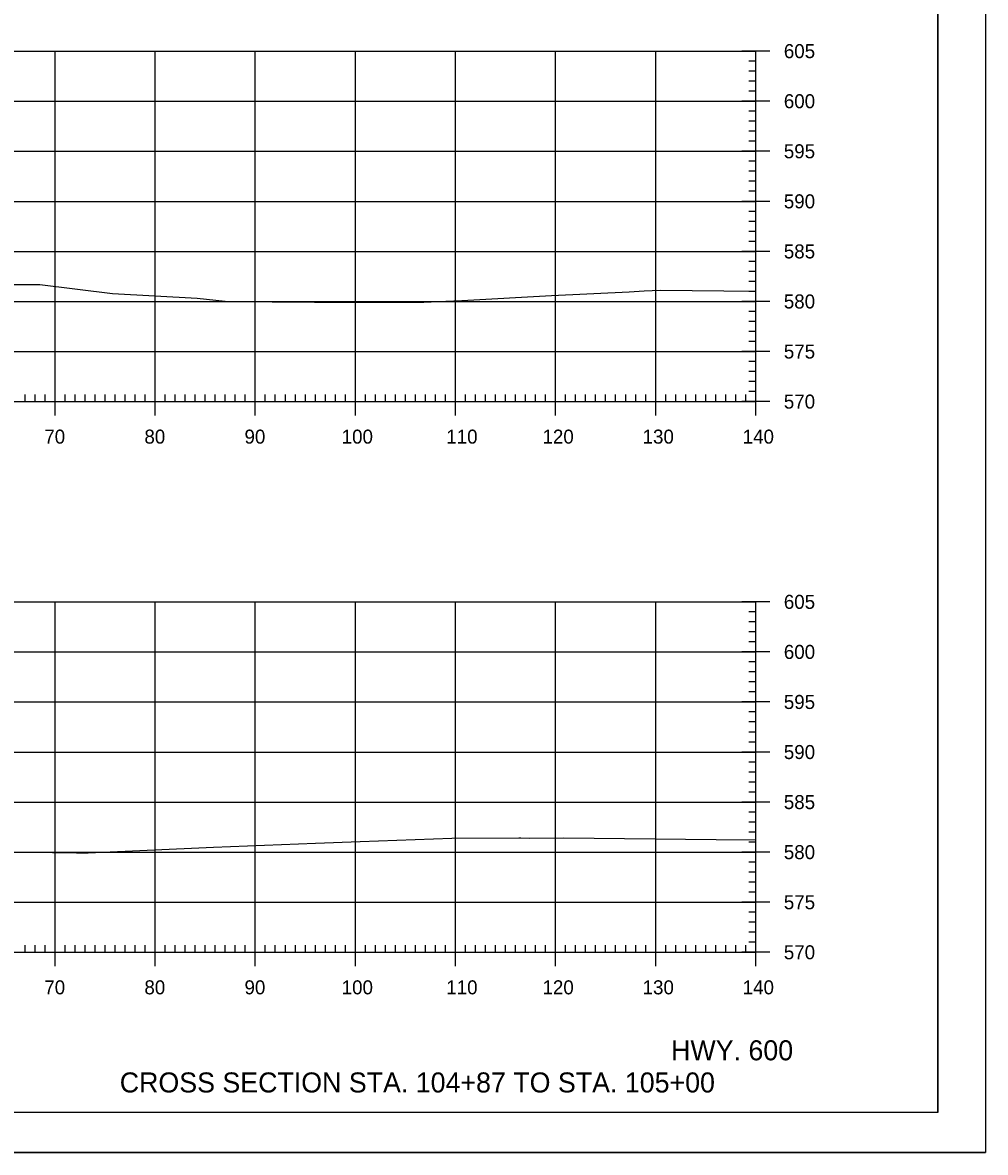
# Model space of a CAD drawing. Extents: x 961436 to 1372525, y 380079 to 2027791.
# Drawn here: x 1370257.3 to 1370353.4, y 380322.4 to 380435.3 of the extents above; entities that cross this region are included whole.
import ezdxf

# ---------------------------------------------------------------- set-up
doc = ezdxf.new("R2010")
doc.units = 0
for name, color, linetype in [('R_Axis', 7, 'Continuous'), ('R_Axis Annot', 7, 'Continuous'), ('R_Draft', 7, 'Continuous'), ('R_Exist Surface', 7, 'Continuous'), ('R_Grid', 7, 'Continuous'), ('R_No Plot', 7, 'Continuous')]:
    doc.layers.add(name, color=color, linetype=linetype)

msp = doc.modelspace()

# ---------------------------------------------------------------- linework, layer by layer
at = {"layer": 'R_Axis'}
for p, q in [((1370331.9, 380432.4), (1370329.1, 380432.4)), ((1370330.5, 380397.4), (1370330.5, 380432.4)), ((1370330.5, 380431.4), (1370329.8, 380431.4)), ((1370330.5, 380430.4), (1370329.8, 380430.4)), ((1370330.5, 380429.4), (1370329.8, 380429.4)), ((1370330.5, 380428.4), (1370329.8, 380428.4)), ((1370331.9, 380427.4), (1370329.1, 380427.4)), ((1370330.5, 380426.4), (1370329.8, 380426.4)), ((1370330.5, 380425.4), (1370329.8, 380425.4)), ((1370330.5, 380424.4), (1370329.8, 380424.4)), ((1370330.5, 380423.4), (1370329.8, 380423.4)), ((1370331.9, 380422.4), (1370329.1, 380422.4)), ((1370330.5, 380421.4), (1370329.8, 380421.4)), ((1370330.5, 380420.4), (1370329.8, 380420.4)), ((1370330.5, 380419.4), (1370329.8, 380419.4)), ((1370330.5, 380418.4), (1370329.8, 380418.4)), ((1370331.9, 380417.4), (1370329.1, 380417.4)), ((1370330.5, 380416.4), (1370329.8, 380416.4)), ((1370330.5, 380415.4), (1370329.8, 380415.4)), ((1370330.5, 380414.4), (1370329.8, 380414.4)), ((1370330.5, 380413.4), (1370329.8, 380413.4)), ((1370331.9, 380412.4), (1370329.1, 380412.4)), ((1370330.5, 380411.4), (1370329.8, 380411.4)), ((1370330.5, 380410.4), (1370329.8, 380410.4)), ((1370330.5, 380409.4), (1370329.8, 380409.4)), ((1370330.5, 380408.4), (1370329.8, 380408.4)), ((1370331.9, 380407.4), (1370329.1, 380407.4)), ((1370330.5, 380406.4), (1370329.8, 380406.4)), ((1370330.5, 380405.4), (1370329.8, 380405.4)), ((1370330.5, 380404.4), (1370329.8, 380404.4)), ((1370331.9, 380402.4), (1370329.1, 380402.4)), ((1370330.5, 380403.4), (1370329.8, 380403.4)), ((1370330.5, 380401.4), (1370329.8, 380401.4)), ((1370330.5, 380400.4), (1370329.8, 380400.4)), ((1370330.5, 380399.4), (1370329.8, 380399.4)), ((1370257.5, 380397.4), (1370257.5, 380398.1)), ((1370258.5, 380397.4), (1370258.5, 380398.1)), ((1370259.5, 380397.4), (1370259.5, 380398.1)), ((1370260.5, 380396), (1370260.5, 380398.8)), ((1370261.5, 380397.4), (1370261.5, 380398.1)), ((1370262.5, 380397.4), (1370262.5, 380398.1)), ((1370263.5, 380397.4), (1370263.5, 380398.1)), ((1370264.5, 380397.4), (1370264.5, 380398.1)), ((1370265.5, 380397.4), (1370265.5, 380398.1)), ((1370266.5, 380397.4), (1370266.5, 380398.1)), ((1370267.5, 380397.4), (1370267.5, 380398.1)), ((1370268.5, 380397.4), (1370268.5, 380398.1)), ((1370269.5, 380397.4), (1370269.5, 380398.1)), ((1370270.5, 380396), (1370270.5, 380398.8)), ((1370271.5, 380397.4), (1370271.5, 380398.1)), ((1370272.5, 380397.4), (1370272.5, 380398.1)), ((1370273.5, 380397.4), (1370273.5, 380398.1)), ((1370274.5, 380397.4), (1370274.5, 380398.1)), ((1370275.5, 380397.4), (1370275.5, 380398.1)), ((1370276.5, 380397.4), (1370276.5, 380398.1)), ((1370277.5, 380397.4), (1370277.5, 380398.1)), ((1370278.5, 380397.4), (1370278.5, 380398.1)), ((1370279.5, 380397.4), (1370279.5, 380398.1)), ((1370280.5, 380396), (1370280.5, 380398.8)), ((1370281.5, 380397.4), (1370281.5, 380398.1)), ((1370282.5, 380397.4), (1370282.5, 380398.1)), ((1370283.5, 380397.4), (1370283.5, 380398.1)), ((1370284.5, 380397.4), (1370284.5, 380398.1)), ((1370285.5, 380397.4), (1370285.5, 380398.1)), ((1370286.5, 380397.4), (1370286.5, 380398.1)), ((1370287.5, 380397.4), (1370287.5, 380398.1)), ((1370288.5, 380397.4), (1370288.5, 380398.1)), ((1370289.5, 380397.4), (1370289.5, 380398.1)), ((1370290.5, 380396), (1370290.5, 380398.8)), ((1370291.5, 380397.4), (1370291.5, 380398.1)), ((1370292.5, 380397.4), (1370292.5, 380398.1)), ((1370293.5, 380397.4), (1370293.5, 380398.1)), ((1370294.5, 380397.4), (1370294.5, 380398.1)), ((1370295.5, 380397.4), (1370295.5, 380398.1)), ((1370296.5, 380397.4), (1370296.5, 380398.1)), ((1370297.5, 380397.4), (1370297.5, 380398.1)), ((1370298.5, 380397.4), (1370298.5, 380398.1)), ((1370299.5, 380397.4), (1370299.5, 380398.1)), ((1370300.5, 380396), (1370300.5, 380398.8)), ((1370301.5, 380397.4), (1370301.5, 380398.1)), ((1370302.5, 380397.4), (1370302.5, 380398.1)), ((1370303.5, 380397.4), (1370303.5, 380398.1)), ((1370304.5, 380397.4), (1370304.5, 380398.1)), ((1370305.5, 380397.4), (1370305.5, 380398.1)), ((1370306.5, 380397.4), (1370306.5, 380398.1)), ((1370307.5, 380397.4), (1370307.5, 380398.1)), ((1370308.5, 380397.4), (1370308.5, 380398.1)), ((1370309.5, 380397.4), (1370309.5, 380398.1)), ((1370310.5, 380396), (1370310.5, 380398.8)), ((1370311.5, 380397.4), (1370311.5, 380398.1)), ((1370312.5, 380397.4), (1370312.5, 380398.1)), ((1370313.5, 380397.4), (1370313.5, 380398.1)), ((1370314.5, 380397.4), (1370314.5, 380398.1)), ((1370315.5, 380397.4), (1370315.5, 380398.1)), ((1370316.5, 380397.4), (1370316.5, 380398.1)), ((1370317.5, 380397.4), (1370317.5, 380398.1)), ((1370318.5, 380397.4), (1370318.5, 380398.1)), ((1370319.5, 380397.4), (1370319.5, 380398.1)), ((1370320.5, 380396), (1370320.5, 380398.8)), ((1370321.5, 380397.4), (1370321.5, 380398.1)), ((1370322.5, 380397.4), (1370322.5, 380398.1)), ((1370323.5, 380397.4), (1370323.5, 380398.1)), ((1370324.5, 380397.4), (1370324.5, 380398.1)), ((1370325.5, 380397.4), (1370325.5, 380398.1)), ((1370326.5, 380397.4), (1370326.5, 380398.1)), ((1370327.5, 380397.4), (1370327.5, 380398.1)), ((1370328.5, 380397.4), (1370328.5, 380398.1)), ((1370329.5, 380397.4), (1370329.5, 380398.1)), ((1370330.5, 380398.4), (1370329.8, 380398.4)), ((1370330.5, 380396), (1370330.5, 380398.8)), ((1370050.5, 380397.4), (1370330.5, 380397.4)), ((1370331.9, 380397.4), (1370329.1, 380397.4)), ((1370331.9, 380377.4), (1370329.1, 380377.4)), ((1370330.5, 380342.4), (1370330.5, 380377.4)), ((1370330.5, 380376.4), (1370329.8, 380376.4)), ((1370330.5, 380375.4), (1370329.8, 380375.4)), ((1370330.5, 380374.4), (1370329.8, 380374.4)), ((1370330.5, 380373.4), (1370329.8, 380373.4)), ((1370331.9, 380372.4), (1370329.1, 380372.4)), ((1370330.5, 380371.4), (1370329.8, 380371.4)), ((1370330.5, 380370.4), (1370329.8, 380370.4)), ((1370330.5, 380369.4), (1370329.8, 380369.4)), ((1370331.9, 380367.4), (1370329.1, 380367.4)), ((1370330.5, 380368.4), (1370329.8, 380368.4)), ((1370330.5, 380366.4), (1370329.8, 380366.4)), ((1370330.5, 380365.4), (1370329.8, 380365.4)), ((1370330.5, 380364.4), (1370329.8, 380364.4)), ((1370330.5, 380363.4), (1370329.8, 380363.4)), ((1370331.9, 380362.4), (1370329.1, 380362.4)), ((1370330.5, 380361.4), (1370329.8, 380361.4)), ((1370330.5, 380360.4), (1370329.8, 380360.4)), ((1370330.5, 380359.4), (1370329.8, 380359.4)), ((1370330.5, 380358.4), (1370329.8, 380358.4)), ((1370331.9, 380357.4), (1370329.1, 380357.4)), ((1370330.5, 380356.4), (1370329.8, 380356.4)), ((1370330.5, 380355.4), (1370329.8, 380355.4)), ((1370330.5, 380354.4), (1370329.8, 380354.4)), ((1370330.5, 380353.4), (1370329.8, 380353.4)), ((1370331.9, 380352.4), (1370329.1, 380352.4)), ((1370330.5, 380351.4), (1370329.8, 380351.4)), ((1370330.5, 380350.4), (1370329.8, 380350.4)), ((1370330.5, 380349.4), (1370329.8, 380349.4)), ((1370330.5, 380348.4), (1370329.8, 380348.4)), ((1370331.9, 380347.4), (1370329.1, 380347.4)), ((1370330.5, 380346.4), (1370329.8, 380346.4)), ((1370330.5, 380345.4), (1370329.8, 380345.4)), ((1370260.5, 380341), (1370260.5, 380343.8)), ((1370270.5, 380341), (1370270.5, 380343.8)), ((1370280.5, 380341), (1370280.5, 380343.8)), ((1370290.5, 380341), (1370290.5, 380343.8)), ((1370300.5, 380341), (1370300.5, 380343.8)), ((1370310.5, 380341), (1370310.5, 380343.8)), ((1370320.5, 380341), (1370320.5, 380343.8)), ((1370330.5, 380344.4), (1370329.8, 380344.4)), ((1370330.5, 380341), (1370330.5, 380343.8)), ((1370257.5, 380342.4), (1370257.5, 380343.1)), ((1370258.5, 380342.4), (1370258.5, 380343.1)), ((1370259.5, 380342.4), (1370259.5, 380343.1)), ((1370261.5, 380342.4), (1370261.5, 380343.1)), ((1370262.5, 380342.4), (1370262.5, 380343.1)), ((1370263.5, 380342.4), (1370263.5, 380343.1)), ((1370264.5, 380342.4), (1370264.5, 380343.1)), ((1370265.5, 380342.4), (1370265.5, 380343.1)), ((1370266.5, 380342.4), (1370266.5, 380343.1)), ((1370267.5, 380342.4), (1370267.5, 380343.1)), ((1370268.5, 380342.4), (1370268.5, 380343.1)), ((1370269.5, 380342.4), (1370269.5, 380343.1)), ((1370271.5, 380342.4), (1370271.5, 380343.1)), ((1370272.5, 380342.4), (1370272.5, 380343.1)), ((1370273.5, 380342.4), (1370273.5, 380343.1)), ((1370274.5, 380342.4), (1370274.5, 380343.1)), ((1370275.5, 380342.4), (1370275.5, 380343.1)), ((1370276.5, 380342.4), (1370276.5, 380343.1)), ((1370277.5, 380342.4), (1370277.5, 380343.1)), ((1370278.5, 380342.4), (1370278.5, 380343.1)), ((1370279.5, 380342.4), (1370279.5, 380343.1)), ((1370281.5, 380342.4), (1370281.5, 380343.1)), ((1370282.5, 380342.4), (1370282.5, 380343.1)), ((1370283.5, 380342.4), (1370283.5, 380343.1)), ((1370284.5, 380342.4), (1370284.5, 380343.1)), ((1370285.5, 380342.4), (1370285.5, 380343.1)), ((1370286.5, 380342.4), (1370286.5, 380343.1)), ((1370287.5, 380342.4), (1370287.5, 380343.1)), ((1370288.5, 380342.4), (1370288.5, 380343.1)), ((1370289.5, 380342.4), (1370289.5, 380343.1)), ((1370291.5, 380342.4), (1370291.5, 380343.1)), ((1370292.5, 380342.4), (1370292.5, 380343.1)), ((1370293.5, 380342.4), (1370293.5, 380343.1)), ((1370294.5, 380342.4), (1370294.5, 380343.1)), ((1370295.5, 380342.4), (1370295.5, 380343.1)), ((1370296.5, 380342.4), (1370296.5, 380343.1)), ((1370297.5, 380342.4), (1370297.5, 380343.1)), ((1370298.5, 380342.4), (1370298.5, 380343.1)), ((1370299.5, 380342.4), (1370299.5, 380343.1)), ((1370301.5, 380342.4), (1370301.5, 380343.1)), ((1370302.5, 380342.4), (1370302.5, 380343.1)), ((1370303.5, 380342.4), (1370303.5, 380343.1)), ((1370304.5, 380342.4), (1370304.5, 380343.1)), ((1370305.5, 380342.4), (1370305.5, 380343.1)), ((1370306.5, 380342.4), (1370306.5, 380343.1)), ((1370307.5, 380342.4), (1370307.5, 380343.1)), ((1370308.5, 380342.4), (1370308.5, 380343.1)), ((1370309.5, 380342.4), (1370309.5, 380343.1)), ((1370311.5, 380342.4), (1370311.5, 380343.1)), ((1370312.5, 380342.4), (1370312.5, 380343.1)), ((1370313.5, 380342.4), (1370313.5, 380343.1)), ((1370314.5, 380342.4), (1370314.5, 380343.1)), ((1370315.5, 380342.4), (1370315.5, 380343.1)), ((1370316.5, 380342.4), (1370316.5, 380343.1)), ((1370317.5, 380342.4), (1370317.5, 380343.1)), ((1370318.5, 380342.4), (1370318.5, 380343.1)), ((1370319.5, 380342.4), (1370319.5, 380343.1)), ((1370321.5, 380342.4), (1370321.5, 380343.1)), ((1370322.5, 380342.4), (1370322.5, 380343.1)), ((1370323.5, 380342.4), (1370323.5, 380343.1)), ((1370324.5, 380342.4), (1370324.5, 380343.1)), ((1370325.5, 380342.4), (1370325.5, 380343.1)), ((1370326.5, 380342.4), (1370326.5, 380343.1)), ((1370327.5, 380342.4), (1370327.5, 380343.1)), ((1370328.5, 380342.4), (1370328.5, 380343.1)), ((1370329.5, 380342.4), (1370329.5, 380343.1)), ((1370330.5, 380343.4), (1370329.8, 380343.4)), ((1370050.5, 380342.4), (1370330.5, 380342.4)), ((1370331.9, 380342.4), (1370329.1, 380342.4))]:
    msp.add_line(p, q, dxfattribs=at)
at = {"layer": 'R_Exist Surface'}
for points in [[(1370251.88, 380409.09), (1370258.99, 380409.09), (1370266.25, 380408.18), (1370274.68, 380407.74), (1370277.5, 380407.42), (1370282.17, 380407.35), (1370286.41, 380407.33), (1370297.34, 380407.32), (1370299.55, 380407.42), (1370301.12, 380407.48), (1370310.08, 380407.98), (1370317.84, 380408.36), (1370319.35, 380408.45), (1370320.94, 380408.52), (1370330.5, 380408.42)], [(1370252.95, 380352.45), (1370257.8, 380352.39), (1370262.63, 380352.32), (1370263.81, 380352.32), (1370276.32, 380352.91), (1370286.52, 380353.29), (1370290.96, 380353.48), (1370300.14, 380353.8), (1370306.83, 380353.82), (1370307.03, 380353.82), (1370307.88, 380353.81), (1370311.28, 380353.83), (1370326.53, 380353.67), (1370330.5, 380353.62)]]:
    msp.add_lwpolyline(points, dxfattribs=at)
at = {"layer": 'R_Grid'}
for p, q in [((1370050.5, 380432.4), (1370330.5, 380432.4)), ((1370260.5, 380397.4), (1370260.5, 380432.4)), ((1370270.5, 380397.4), (1370270.5, 380432.4)), ((1370280.5, 380397.4), (1370280.5, 380432.4)), ((1370290.5, 380397.4), (1370290.5, 380432.4)), ((1370300.5, 380397.4), (1370300.5, 380432.4)), ((1370310.5, 380397.4), (1370310.5, 380432.4)), ((1370320.5, 380397.4), (1370320.5, 380432.4)), ((1370330.5, 380397.4), (1370330.5, 380432.4)), ((1370050.5, 380427.4), (1370330.5, 380427.4)), ((1370050.5, 380422.4), (1370330.5, 380422.4)), ((1370050.5, 380417.4), (1370330.5, 380417.4)), ((1370050.5, 380412.4), (1370330.5, 380412.4)), ((1370050.5, 380407.4), (1370330.5, 380407.4)), ((1370050.5, 380402.4), (1370330.5, 380402.4)), ((1370050.5, 380397.4), (1370330.5, 380397.4)), ((1370050.5, 380377.4), (1370330.5, 380377.4)), ((1370260.5, 380342.4), (1370260.5, 380377.4)), ((1370270.5, 380342.4), (1370270.5, 380377.4)), ((1370280.5, 380342.4), (1370280.5, 380377.4)), ((1370290.5, 380342.4), (1370290.5, 380377.4)), ((1370300.5, 380342.4), (1370300.5, 380377.4)), ((1370310.5, 380342.4), (1370310.5, 380377.4)), ((1370320.5, 380342.4), (1370320.5, 380377.4)), ((1370330.5, 380342.4), (1370330.5, 380377.4)), ((1370050.5, 380372.4), (1370330.5, 380372.4)), ((1370050.5, 380367.4), (1370330.5, 380367.4)), ((1370050.5, 380362.4), (1370330.5, 380362.4)), ((1370050.5, 380357.4), (1370330.5, 380357.4)), ((1370050.5, 380352.4), (1370330.5, 380352.4)), ((1370050.5, 380347.4), (1370330.5, 380347.4)), ((1370050.5, 380342.4), (1370330.5, 380342.4))]:
    msp.add_line(p, q, dxfattribs=at)
at = {"layer": 'R_No Plot'}
for p, q in [((1370348.68, 380326.4), (1370348.68, 380531.86)), ((1370348.68, 380326.4), (1370032.5, 380326.4)), ((1370020.1, 380322.42), (1370353.44, 380322.42))]:
    msp.add_line(p, q, dxfattribs=at)
for points in [[(1370020.1, 380535.75), (1370353.44, 380535.75), (1370353.44, 380322.41), (1370020.1, 380322.41)], [(1370266.42, 380531.86), (1370286.04, 380531.86), (1370286.04, 380521.98), (1370302.16, 380521.98), (1370325.36, 380521.98), (1370325.48, 380493.82), (1370348.68, 380493.82), (1370348.68, 380326.4), (1370032.5, 380326.4), (1370032.5, 380531.86)]]:
    msp.add_lwpolyline(points, close=True, dxfattribs=at)

# ---------------------------------------------------------------- texts
at = {"layer": 'R_Axis Annot'}
for s, p in [('605', (1370333.3, 380431.7)), ('600', (1370333.3, 380426.7)), ('595', (1370333.3, 380421.7)), ('590', (1370333.3, 380416.7)), ('585', (1370333.3, 380411.7)), ('580', (1370333.3, 380406.7)), ('575', (1370333.3, 380401.7)), ('570', (1370333.3, 380396.7)), ('70', (1370259.42, 380393.2)), ('80', (1370269.42, 380393.2)), ('90', (1370279.42, 380393.2)), ('100', (1370289.13, 380393.2)), ('110', (1370299.58, 380393.2)), ('120', (1370309.19, 380393.2)), ('130', (1370319.19, 380393.2)), ('140', (1370329.19, 380393.2)), ('605', (1370333.3, 380376.7)), ('600', (1370333.3, 380371.7)), ('595', (1370333.3, 380366.7)), ('590', (1370333.3, 380361.7)), ('585', (1370333.3, 380356.7)), ('580', (1370333.3, 380351.7)), ('575', (1370333.3, 380346.7)), ('570', (1370333.3, 380341.7)), ('70', (1370259.42, 380338.2)), ('80', (1370269.42, 380338.2)), ('90', (1370279.42, 380338.2)), ('100', (1370289.13, 380338.2)), ('110', (1370299.58, 380338.2)), ('120', (1370309.19, 380338.2)), ('130', (1370319.19, 380338.2)), ('140', (1370329.19, 380338.2))]:
    msp.add_text(s, height=1.4, dxfattribs=at).set_placement(p)
at = {"layer": 'R_Draft'}
for s, p in [('HWY. 600', (1370322.04, 380331.61)), ('CROSS SECTION STA. 104+87 TO STA. 105+00', (1370266.96, 380328.4))]:
    msp.add_text(s, height=2, dxfattribs=at).set_placement(p)

doc.saveas('drawing.dxf')
